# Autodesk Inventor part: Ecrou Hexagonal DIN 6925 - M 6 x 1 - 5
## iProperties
Created: 2002-09
Part Number: Ecrou Hexagonal DIN 6925 - M 6 x 1 - 5
Material: Par défaut
Catalog Web Link: www.traceparts.com
Description: Ecrou Hexagonal DIN 6925 - M 6 x 1 - 5
Document SubType Name: Modélisation
Designer: Maison
Control State: 0
Master: False
Checked Out: False
Shininess: 20.0
Length Units: 11269
Angle Units: 11279
Time Units: 11290
Mass Units: 11283
Length Display Precision: 3
Angle Display Precision: 2
Density: 0.0
Volumn: 0.0
Area: 0.0
PropertySet Name: Model Information
Author: Maison
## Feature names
1. Base1
